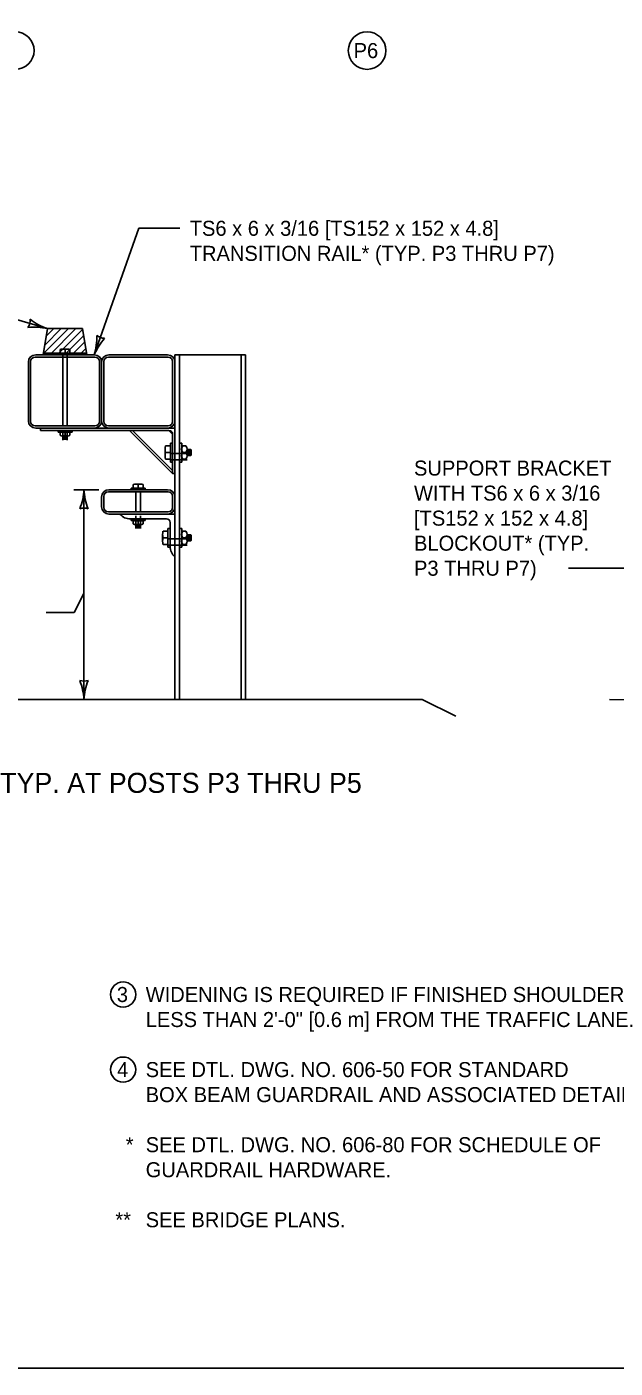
# Model space of a CAD drawing. Extents: x 49983 to 50021, y 49963.5 to 50011.4.
# Drawn here: x 50008.99 to 50011.34, y 49987.8 to 49993.16 of the extents above; entities that cross this region are included whole.
import ezdxf

# ---------------------------------------------------------------- set-up
doc = ezdxf.new("R2010")
doc.units = 0
for name, color, linetype in [('Level 1', 7, 'Continuous'), ('Level 10', 7, 'Continuous'), ('Level 2', 7, 'Continuous'), ('Level 3', 7, 'Continuous'), ('Level 4', 7, 'Continuous')]:
    doc.layers.add(name, color=color, linetype=linetype)

msp = doc.modelspace()

# ---------------------------------------------------------------- linework, layer by layer
at = {"layer": 'Level 1'}
for p, q in [((50009.0511, 49991.8474), (50009.0687, 49991.952)), ((50009.0517, 49991.8508), (50009.1527, 49991.952)), ((50009.0577, 49991.8864), (50009.1231, 49991.952)), ((50009.0636, 49991.922), (50009.0937, 49991.952)), ((50009.0687, 49991.952), (50009.2082, 49991.952)), ((50009.0777, 49991.8474), (50009.1825, 49991.952)), ((50009.2082, 49991.952), (50009.2258, 49991.8474)), ((50009.1072, 49991.8474), (50009.2088, 49991.9488)), ((50009.137, 49991.8474), (50009.213, 49991.9234)), ((50009.1667, 49991.8474), (50009.2173, 49991.8981)), ((50009.0219, 49991.8474), (50009.2561, 49991.8474)), ((50009.2258, 49991.8474), (50009.0511, 49991.8474)), ((50009.1963, 49991.8474), (50009.2216, 49991.8728)), ((50009.3147, 49991.8474), (50009.5489, 49991.8474)), ((50009.5782, 49991.8474), (50009.5782, 49991.5545)), ((50009.5782, 49991.6552), (50009.5782, 49991.8474)), ((50009.8604, 49991.8474), (50009.5782, 49991.8474)), ((50009.5782, 49990.4704), (50009.5782, 49991.8474)), ((50009.5962, 49990.4704), (50009.5962, 49991.8474)), ((50009.8424, 49991.7691), (50009.8424, 49991.8474)), ((50009.8424, 49990.4704), (50009.8424, 49991.8474)), ((50009.8604, 49990.4704), (50009.8604, 49991.8474)), ((50008.9926, 49991.8181), (50008.9926, 49991.5838)), ((50009.0017, 49991.8206), (50009.0017, 49991.5813)), ((50009.0193, 49991.8382), (50009.2587, 49991.8382)), ((50009.1298, 49991.5637), (50009.1298, 49991.8382)), ((50009.1481, 49991.5637), (50009.1481, 49991.8382)), ((50009.2763, 49991.8206), (50009.2763, 49991.5813)), ((50009.2854, 49991.8181), (50009.2854, 49991.5838)), ((50009.2854, 49991.8181), (50009.2854, 49991.5838)), ((50009.2945, 49991.8206), (50009.2945, 49991.5813)), ((50009.3121, 49991.8382), (50009.5515, 49991.8382)), ((50009.5691, 49991.8206), (50009.5691, 49991.5813)), ((50009.5782, 49991.7513), (50009.5782, 49991.7513)), ((50009.8424, 49991.6552), (50009.8424, 49991.7336)), ((50009.0193, 49991.5637), (50009.2587, 49991.5637)), ((50009.0219, 49991.5545), (50009.2854, 49991.5545)), ((50009.0413, 49991.5545), (50009.5782, 49991.5545)), ((50009.0413, 49991.5454), (50009.0413, 49991.5545)), ((50009.0413, 49991.5454), (50009.5544, 49991.5454)), ((50009.1112, 49991.5388), (50009.1112, 49991.5454)), ((50009.1672, 49991.5388), (50009.1112, 49991.5388)), ((50009.1192, 49991.5259), (50009.1192, 49991.5358)), ((50009.1489, 49991.5228), (50009.1291, 49991.5228)), ((50009.1298, 49991.512), (50009.1298, 49991.5228)), ((50009.139, 49991.5358), (50009.139, 49991.5259)), ((50009.1481, 49991.512), (50009.1481, 49991.5228)), ((50009.1587, 49991.5259), (50009.1587, 49991.5358)), ((50009.1672, 49991.5388), (50009.1672, 49991.5454)), ((50009.2854, 49991.5545), (50009.5782, 49991.5545)), ((50009.3121, 49991.5637), (50009.5515, 49991.5637)), ((50009.5691, 49991.3727), (50009.3965, 49991.5453)), ((50009.4093, 49991.5454), (50009.5691, 49991.3857)), ((50009.5544, 49991.5454), (50009.5691, 49991.5308)), ((50009.5691, 49991.5308), (50009.5691, 49991.3727)), ((50009.5782, 49991.5545), (50009.5782, 49991.3727)), ((50009.1481, 49991.512), (50009.1298, 49991.512)), ((50009.1298, 49991.512), (50009.1317, 49991.5102)), ((50009.1317, 49991.5102), (50009.1463, 49991.5102)), ((50009.1325, 49991.5203), (50009.1453, 49991.5203)), ((50009.1325, 49991.5184), (50009.1453, 49991.5184)), ((50009.1325, 49991.5166), (50009.1453, 49991.5166)), ((50009.1325, 49991.5148), (50009.1453, 49991.5148)), ((50009.1481, 49991.512), (50009.1463, 49991.5102)), ((50009.5388, 49991.4437), (50009.5388, 49991.4702)), ((50009.5404, 49991.4834), (50009.5602, 49991.4834)), ((50009.5602, 49991.4191), (50009.5602, 49991.4943)), ((50009.5602, 49991.4943), (50009.5691, 49991.4943)), ((50009.6051, 49991.4943), (50009.5962, 49991.4943)), ((50009.6051, 49991.4191), (50009.6051, 49991.4943)), ((50009.6224, 49991.4834), (50009.6092, 49991.4834)), ((50009.6265, 49991.4437), (50009.6265, 49991.4702)), ((50009.5404, 49991.4569), (50009.5602, 49991.4569)), ((50009.5404, 49991.4304), (50009.5602, 49991.4304)), ((50009.5602, 49991.4191), (50009.5691, 49991.4191)), ((50009.6051, 49991.4191), (50009.5962, 49991.4191)), ((50009.6092, 49991.4569), (50009.6224, 49991.4569)), ((50009.6224, 49991.4304), (50009.6092, 49991.4304)), ((50009.6411, 49991.4692), (50009.6265, 49991.4692)), ((50009.6411, 49991.4446), (50009.6265, 49991.4446)), ((50009.6299, 49991.4482), (50009.6299, 49991.4655)), ((50009.6324, 49991.4482), (50009.6324, 49991.4655)), ((50009.6349, 49991.4482), (50009.6349, 49991.4655)), ((50009.6373, 49991.4482), (50009.6373, 49991.4655)), ((50009.6411, 49991.4692), (50009.6411, 49991.4446)), ((50009.6411, 49991.4692), (50009.6435, 49991.4668)), ((50009.6411, 49991.4446), (50009.6435, 49991.4471)), ((50009.6435, 49991.4471), (50009.6435, 49991.4668)), ((50009.5782, 49991.3727), (50009.5691, 49991.3727)), ((50009.5489, 49991.3086), (50009.3147, 49991.3086)), ((50009.4597, 49991.3152), (50009.4037, 49991.3152)), ((50009.4037, 49991.3152), (50009.4037, 49991.3086)), ((50009.4118, 49991.33), (50009.4118, 49991.3152)), ((50009.4414, 49991.3312), (50009.4216, 49991.3312)), ((50009.4315, 49991.33), (50009.4315, 49991.3152)), ((50009.4513, 49991.33), (50009.4513, 49991.3152)), ((50009.4597, 49991.3152), (50009.4597, 49991.3086)), ((50009.2854, 49991.2793), (50009.2854, 49991.2403)), ((50009.2945, 49991.2819), (50009.2945, 49991.2377)), ((50009.5515, 49991.2995), (50009.3121, 49991.2995)), ((50009.4224, 49991.2201), (50009.4224, 49991.2995)), ((50009.4407, 49991.2201), (50009.4407, 49991.2995)), ((50009.5691, 49991.2819), (50009.5691, 49991.2377)), ((50009.5515, 49991.2201), (50009.3121, 49991.2201)), ((50009.5782, 49991.211), (50009.3147, 49991.211)), ((50009.3586, 49991.211), (50009.5782, 49991.211)), ((50009.4005, 49991.192), (50009.5446, 49991.192)), ((50009.4037, 49991.1854), (50009.4037, 49991.192)), ((50009.4597, 49991.1854), (50009.4037, 49991.1854)), ((50009.4118, 49991.1725), (50009.4118, 49991.1824)), ((50009.4414, 49991.1695), (50009.4216, 49991.1695)), ((50009.4224, 49991.1586), (50009.4224, 49991.1695)), ((50009.4407, 49991.1586), (50009.4224, 49991.1586)), ((50009.4224, 49991.1586), (50009.4242, 49991.1568)), ((50009.4242, 49991.1568), (50009.4388, 49991.1568)), ((50009.425, 49991.1669), (50009.4379, 49991.1669)), ((50009.425, 49991.1651), (50009.4379, 49991.1651)), ((50009.425, 49991.1632), (50009.4379, 49991.1632)), ((50009.425, 49991.1614), (50009.4379, 49991.1614)), ((50009.4315, 49991.1824), (50009.4315, 49991.1725)), ((50009.4407, 49991.1586), (50009.4388, 49991.1568)), ((50009.4407, 49991.1586), (50009.4407, 49991.1695)), ((50009.4513, 49991.1725), (50009.4513, 49991.1824)), ((50009.4597, 49991.1854), (50009.4597, 49991.192)), ((50009.5504, 49991.0784), (50009.5504, 49991.1536)), ((50009.5504, 49991.1536), (50009.5593, 49991.1536)), ((50009.5593, 49991.082), (50009.5593, 49991.1774)), ((50009.6051, 49991.1536), (50009.5962, 49991.1536)), ((50009.6051, 49991.0784), (50009.6051, 49991.1536)), ((50009.529, 49991.103), (50009.529, 49991.1295)), ((50009.5306, 49991.1428), (50009.5504, 49991.1428)), ((50009.5306, 49991.1163), (50009.5504, 49991.1163)), ((50009.6224, 49991.1428), (50009.6092, 49991.1428)), ((50009.6092, 49991.1163), (50009.6224, 49991.1163)), ((50009.6265, 49991.103), (50009.6265, 49991.1295)), ((50009.6411, 49991.1286), (50009.6265, 49991.1286)), ((50009.6411, 49991.104), (50009.6265, 49991.104)), ((50009.6299, 49991.1076), (50009.6299, 49991.1248)), ((50009.6324, 49991.1076), (50009.6324, 49991.1248)), ((50009.6349, 49991.1076), (50009.6349, 49991.1248)), ((50009.6373, 49991.1076), (50009.6373, 49991.1248)), ((50009.6411, 49991.1286), (50009.6411, 49991.104)), ((50009.6411, 49991.1286), (50009.6435, 49991.1261)), ((50009.6411, 49991.104), (50009.6435, 49991.1064)), ((50009.6435, 49991.1064), (50009.6435, 49991.1261)), ((50009.5306, 49991.0898), (50009.5504, 49991.0898)), ((50009.5504, 49991.0784), (50009.5593, 49991.0784)), ((50009.6051, 49991.0784), (50009.5962, 49991.0784)), ((50009.6224, 49991.0898), (50009.6092, 49991.0898)), ((50008.8949, 49990.4704), (50010.5661, 49990.4704)), ((50010.5661, 49990.4704), (50010.7001, 49990.4034)), ((50011.3147, 49990.4704), (50012.9857, 49990.4369))]:
    msp.add_line(p, q, dxfattribs=at)
msp.add_lwpolyline([(49999.3835, 49998.9992), (50016.7501, 49998.9992), (50016.7501, 49987.7988), (49999.3835, 49987.7988)], close=True, dxfattribs=at)
for centre, radius, start, end in [((50009.0219, 49991.8181), 0.0293, 90, 180), ((50009.2561, 49991.8181), 0.0293, 0, 90), ((50009.3147, 49991.8181), 0.0293, 90, 180), ((50009.5489, 49991.8181), 0.0293, 0, 90), ((50009.0193, 49991.8206), 0.0176, 90, 180), ((50009.2587, 49991.8206), 0.0176, 0, 90), ((50009.3121, 49991.8206), 0.0176, 90, 180), ((50009.5515, 49991.8206), 0.0176, 0, 90), ((50009.0219, 49991.5838), 0.0293, 180, 270), ((50009.0193, 49991.5813), 0.0176, 180, 270), ((50009.2561, 49991.5838), 0.0293, 270, 0), ((50009.2587, 49991.5813), 0.0176, 270, 0), ((50009.3147, 49991.5838), 0.0293, 180, 270), ((50009.3121, 49991.5813), 0.0176, 180, 270), ((50009.5489, 49991.5838), 0.0293, 270, 0), ((50009.5515, 49991.5813), 0.0176, 270, 0), ((50009.1291, 49991.5213), 0.0175, 55.616, 124.384), ((50009.1291, 49991.5403), 0.0175, 235.616, 304.384), ((50009.1489, 49991.5213), 0.0175, 55.616, 124.384), ((50009.1489, 49991.5403), 0.0175, 235.616, 304.384), ((50009.5544, 49991.5308), 0.0146, 0, 90), ((50009.5945, 49991.4702), 0.0557, 166.2307, 193.7693), ((50009.6285, 49991.4702), 0.0235, 145.616, 214.384), ((50009.603, 49991.4702), 0.0235, 325.616, 34.384), ((50009.5945, 49991.4437), 0.0557, 166.2307, 193.7693), ((50009.6285, 49991.4437), 0.0235, 145.616, 214.384), ((50009.603, 49991.4437), 0.0235, 325.616, 34.384), ((50009.3147, 49991.2793), 0.0293, 90, 180), ((50009.4216, 49991.2897), 0.0415, 76.2307, 103.7693), ((50009.4414, 49991.2897), 0.0415, 76.2307, 103.7693), ((50009.5489, 49991.2793), 0.0293, 0, 90), ((50009.3121, 49991.2819), 0.0176, 90, 180), ((50009.5515, 49991.2819), 0.0176, 0, 90), ((50009.3147, 49991.2403), 0.0293, 180, 270), ((50009.3121, 49991.2377), 0.0176, 180, 270), ((50009.3987, 49991.2438), 0.0518, 219.3297, 271.9596), ((50009.5489, 49991.2403), 0.0293, 270, 0), ((50009.5515, 49991.2377), 0.0176, 270, 0), ((50009.4216, 49991.168), 0.0175, 55.616, 124.384), ((50009.4216, 49991.1869), 0.0175, 235.616, 304.384), ((50009.4414, 49991.168), 0.0175, 55.616, 124.384), ((50009.4414, 49991.1869), 0.0175, 235.616, 304.384), ((50009.5446, 49991.1774), 0.0146, 0, 90), ((50009.5846, 49991.1295), 0.0557, 166.2307, 193.7693), ((50009.5846, 49991.103), 0.0557, 166.2307, 193.7693), ((50009.6285, 49991.1295), 0.0235, 145.616, 214.384), ((50009.6285, 49991.103), 0.0235, 145.616, 214.384), ((50009.603, 49991.1295), 0.0235, 325.616, 34.384), ((50009.603, 49991.103), 0.0235, 325.616, 34.384), ((50009.6111, 49991.0803), 0.0518, 178.0404, 230.6703)]:
    msp.add_arc(centre, radius, start, end, dxfattribs=at)
at = {"layer": 'Level 10'}
for p, q in [((50009.1298, 49991.5472), (50009.1298, 49991.5063)), ((50009.1481, 49991.5472), (50009.1481, 49991.5063)), ((50009.5603, 49991.4527), (50009.6265, 49991.4527)), ((50009.5603, 49991.4282), (50009.6265, 49991.4282)), ((50009.4224, 49991.283), (50009.4224, 49991.2987)), ((50009.4407, 49991.283), (50009.4407, 49991.2987)), ((50009.4224, 49991.2036), (50009.4224, 49991.153)), ((50009.4407, 49991.2036), (50009.4407, 49991.153)), ((50009.5504, 49991.1121), (50009.6265, 49991.1121)), ((50009.5504, 49991.0875), (50009.6265, 49991.0875))]:
    msp.add_line(p, q, dxfattribs=at)
at = {"layer": 'Level 2'}
for centre, radius in [((50008.9404, 49993.0629), 0.075), ((50010.346, 49993.0629), 0.075), ((50009.3712, 49989.2917), 0.0503), ((50009.3712, 49988.9917), 0.0503)]:
    msp.add_circle(centre, radius, dxfattribs=at)
at = {"layer": 'Level 3'}
for p, q in [((50009.2561, 49991.8474), (50009.4345, 49992.3529)), ((50009.5973, 49992.3529), (50009.4345, 49992.3529)), ((50009.0687, 49991.952), (50008.3742, 49992.1529)), ((50009.2747, 49991.3086), (50009.1747, 49991.3086)), ((50009.2147, 49991.3086), (50009.2147, 49990.4704)), ((50011.1502, 49990.9949), (50011.6129, 49990.9949)), ((50009.1761, 49990.8186), (50009.2147, 49990.8945)), ((50009.0641, 49990.8186), (50009.1761, 49990.8186))]:
    msp.add_line(p, q, dxfattribs=at)
for centre, radius, start, end in [((50008.9455, 49991.9876), 0.0548, 326.0098, 1.7322), ((50009.0151, 49991.7253), 0.233, 76.6983, 95.9482), ((50009.1392, 49992.1629), 0.2223, 231.327, 251.5105), ((50009.0328, 49991.914), 0.233, 343.3872, 2.637), ((50009.4625, 49991.7648), 0.2223, 138.0159, 158.1994), ((50009.2988, 49991.9683), 0.0548, 232.6987, 268.421), ((50008.9926, 49991.3178), 0.2223, 337.456, 357.6395), ((50009.4474, 49991.3201), 0.233, 182.8273, 202.0772), ((50009.2147, 49991.1804), 0.0548, 72.1388, 107.8612), ((50009.2147, 49990.5986), 0.0548, 252.1388, 287.8612), ((50008.982, 49990.4589), 0.233, 2.8273, 22.0772), ((50009.4368, 49990.4612), 0.2223, 157.456, 177.6395)]:
    msp.add_arc(centre, radius, start, end, dxfattribs=at)
at = {"layer": 'Level 4'}
for p, q in [((50009.0522, 49991.8539), (50009.2247, 49991.8539)), ((50009.1192, 49991.8687), (50009.1192, 49991.8539)), ((50009.1291, 49991.8699), (50009.1489, 49991.8699)), ((50009.1298, 49991.8382), (50009.1298, 49991.8539)), ((50009.139, 49991.8687), (50009.139, 49991.8539)), ((50009.1481, 49991.8382), (50009.1481, 49991.8539)), ((50009.1587, 49991.8687), (50009.1587, 49991.8539))]:
    msp.add_line(p, q, dxfattribs=at)
for centre in [(50009.1291, 49991.8284), (50009.1489, 49991.8284)]:
    msp.add_arc(centre, 0.0415, 76.2307, 103.7693, dxfattribs=at)

# ---------------------------------------------------------------- texts
at = {"layer": 'Level 2'}
for s, height, p in [('P6', 0.06, (50010.2922, 49993.033)), ('TS6 x 6 x 3/16 [TS152 x 152 x 4.8]', 0.06, (50009.6373, 49992.3229)), ('TRANSITION RAIL* (TYP. P3 THRU P7)', 0.06, (50009.6373, 49992.2229)), ('SUPPORT BRACKET', 0.06, (50010.5334, 49991.3649)), ('WITH TS6 x 6 x 3/16', 0.06, (50010.5334, 49991.2649)), ('[TS152 x 152 x 4.8]', 0.06, (50010.5334, 49991.1649)), ('BLOCKOUT* (TYP.', 0.06, (50010.5334, 49991.0649)), ('P3 THRU P7)', 0.06, (50010.5334, 49990.9649)), ('TYP. AT POSTS P3 THRU P5', 0.08, (50008.8801, 49990.0973)), ('3', 0.06, (50009.346, 49989.2617)), ('WIDENING IS REQUIRED IF FINISHED SHOULDER IS', 0.06, (50009.4614, 49989.2617)), ('LESS THAN 2\'-0" [0.6 m] FROM THE TRAFFIC LANE.', 0.06, (50009.4614, 49989.1617)), ('4', 0.06, (50009.3473, 49988.9617)), ('SEE DTL. DWG. NO. 606-50 FOR STANDARD', 0.06, (50009.4614, 49988.9617)), ('BOX BEAM GUARDRAIL AND ASSOCIATED DETAILS.', 0.06, (50009.4614, 49988.8617)), ('*', 0.06, (50009.3816, 49988.6617)), ('SEE DTL. DWG. NO. 606-80 FOR SCHEDULE OF', 0.06, (50009.4614, 49988.6617)), ('GUARDRAIL HARDWARE.', 0.06, (50009.4614, 49988.5617)), ('**', 0.06, (50009.3401, 49988.3617)), ('SEE BRIDGE PLANS.', 0.06, (50009.4614, 49988.3617))]:
    msp.add_text(s, height=height, dxfattribs=at).set_placement(p)

doc.saveas('drawing.dxf')
